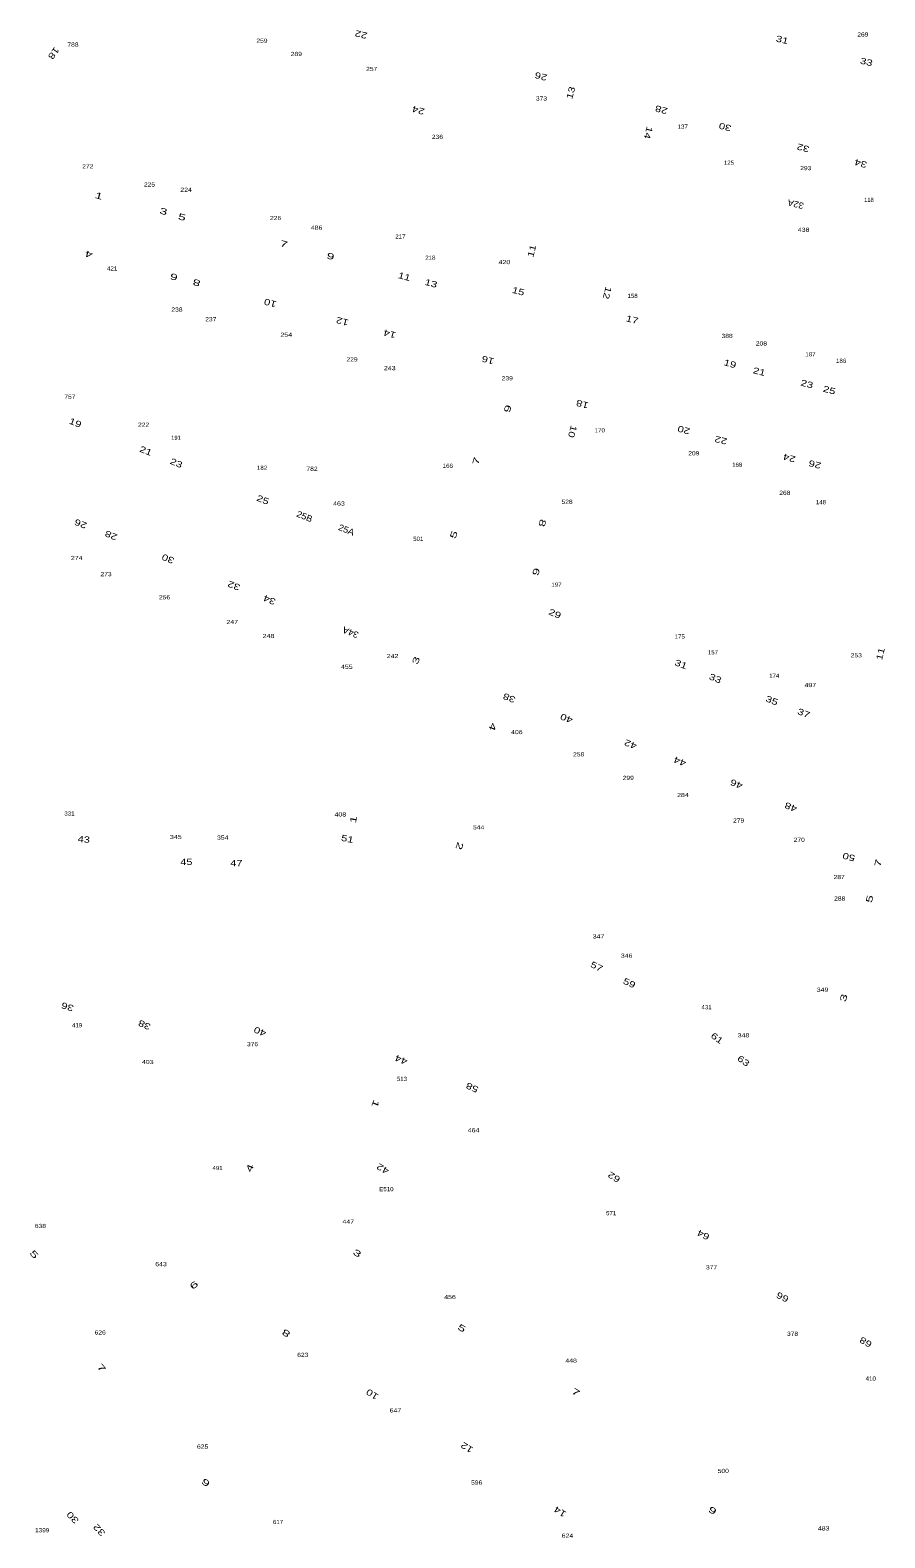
# Model space of a CAD drawing. Extents: x -828673 to -815583, y -1077737 to -1063807.
# Drawn here: x -818529 to -818324.1, y -1069307.9 to -1068946.4 of the extents above; entities that cross this region are included whole.
import ezdxf
from ezdxf.enums import TextEntityAlignment as Align

# ---------------------------------------------------------------- set-up
doc = ezdxf.new("R2010")
doc.units = 0
doc.header["$LTSCALE"] = 0.4
doc.layers.add('1', color=7, linetype='Continuous')
doc.layers.add('2', color=7, linetype='Continuous')

msp = doc.modelspace()

# ---------------------------------------------------------------- texts
at = {"layer": '1'}
for s, width, p in [('788', 1.2, (-818518.729, -1068950.34)), ('259', 1.2, (-818473.433, -1068949.416)), ('269', 1.2, (-818329.403, -1068947.924)), ('289', 1.2, (-818465.19, -1068952.588)), ('257', 1.2, (-818447.118, -1068956.183)), ('373', 1.2, (-818406.43, -1068963.268)), ('137', 1.1, (-818372.57, -1068970.008)), ('236', 1.2, (-818431.371, -1068972.467)), ('125', 1.1, (-818361.499, -1068978.661)), ('272', 1.2, (-818515.178, -1068979.552)), ('293', 1.2, (-818343.075, -1068979.959)), ('225', 1.2, (-818500.382, -1068983.887)), ('224', 1.25, (-818491.61, -1068985.156)), ('226', 1.2, (-818470.157, -1068991.924)), ('486', 1.25, (-818460.328, -1068994.25)), ('217', 1.1, (-818440.248, -1068996.365)), ('438', 1.25, (-818343.594, -1068994.757)), ('421', 1.1, (-818509.34, -1069004.03)), ('218', 1.1, (-818433.062, -1069001.44)), ('420', 1.25, (-818415.307, -1069002.498)), ('158', 1.1, (-818384.593, -1069010.593)), ('238', 1.2, (-818493.805, -1069013.889)), ('237', 1.2, (-818485.69, -1069016.209)), ('254', 1.25, (-818467.605, -1069019.92)), ('388', 1.2, (-818361.931, -1069020.198)), ('208', 1.2, (-818353.714, -1069022.016)), ('229', 1.2, (-818451.838, -1069025.836)), ('187', 1.1, (-818341.951, -1069024.612)), ('186', 1.1, (-818334.599, -1069026.169)), ('243', 1.25, (-818442.795, -1069027.923)), ('239', 1.2, (-818414.624, -1069030.359)), ('757', 1.2, (-818519.462, -1069034.769)), ('222', 1.2, (-818501.805, -1069041.494)), ('170', 1.1, (-818392.441, -1069042.838)), ('182', 1.1, (-818473.401, -1069051.817)), ('166', 1.1, (-818428.883, -1069051.353)), ('209', 1.2, (-818369.912, -1069048.346)), ('168', 1.1, (-818359.513, -1069051.1)), ('782', 1.2, (-818461.426, -1069052.068)), ('268', 1.2, (-818348.095, -1069057.831)), ('463', 1.25, (-818454.968, -1069060.4)), ('528', 1.2, (-818400.291, -1069059.973)), ('148', 1.1, (-818339.43, -1069060.075)), ('501', 1.1, (-818435.955, -1069068.867)), ('274', 1.25, (-818517.817, -1069073.454)), ('273', 1.2, (-818510.803, -1069077.328)), ('197', 1.1, (-818402.84, -1069079.862)), ('256', 1.2, (-818496.775, -1069082.884)), ('247', 1.25, (-818480.554, -1069088.805)), ('248', 1.25, (-818471.86, -1069092.167)), ('175', 1.1, (-818373.276, -1069092.305)), ('242', 1.25, (-818442.107, -1069096.974)), ('157', 1.1, (-818365.324, -1069096.079)), ('253', 1.2, (-818330.969, -1069096.793)), ('455', 1.25, (-818453.082, -1069099.551)), ('174', 1.1, (-818350.644, -1069101.688)), ('497', 1.25, (-818341.979, -1069103.932)), ('406', 1.25, (-818412.334, -1069115.2)), ('258', 1.2, (-818397.516, -1069120.534)), ('299', 1.2, (-818385.632, -1069126.19)), ('284', 1.25, (-818372.526, -1069130.303)), ('331', 1.1, (-818519.574, -1069134.733)), ('408', 1.25, (-818454.625, -1069134.958)), ('544', 1.2, (-818421.487, -1069138.039)), ('279', 1.2, (-818359.164, -1069136.409)), ('345', 1.25, (-818494.074, -1069140.362)), ('354', 1.25, (-818482.822, -1069140.508)), ('270', 1.2, (-818344.646, -1069141.037)), ('287', 1.2, (-818335.074, -1069149.97)), ('288', 1.2, (-818334.945, -1069155.112)), ('347', 1.25, (-818392.758, -1069164.203)), ('346', 1.25, (-818386.012, -1069168.83)), ('349', 1.25, (-818339.052, -1069176.993)), ('431', 1.1, (-818366.858, -1069181.181)), ('419', 1.1, (-818517.732, -1069185.507)), ('348', 1.25, (-818358.003, -1069187.919)), ('376', 1.2, (-818475.68, -1069190.039)), ('403', 1.25, (-818500.791, -1069194.321)), ('513', 1.1, (-818439.87, -1069198.371)), ('464', 1.25, (-818422.703, -1069210.688)), ('491', 1.1, (-818484.076, -1069219.744)), ('E510', 1.1, (-818443.597, -1069224.812)), ('447', 1.25, (-818452.745, -1069232.608)), ('571', 1.1, (-818389.725, -1069230.574)), ('638', 1.2, (-818526.542, -1069233.642)), ('643', 1.25, (-818497.629, -1069242.795)), ('377', 1.2, (-818365.669, -1069243.569)), ('456', 1.25, (-818428.35, -1069250.687)), ('626', 1.2, (-818512.198, -1069259.179)), ('378', 1.2, (-818346.243, -1069259.501)), ('623', 1.2, (-818463.643, -1069264.555)), ('448', 1.25, (-818399.325, -1069265.941)), ('410', 1.1, (-818327.496, -1069270.235)), ('647', 1.25, (-818441.434, -1069277.871)), ('625', 1.2, (-818487.646, -1069286.541)), ('596', 1.2, (-818421.961, -1069295.176)), ('617', 1.1, (-818469.571, -1069304.624)), ('1399', 1.15, (-818526.1, -1069306.601)), ('624', 1.25, (-818400.205, -1069307.921)), ('483', 1.25, (-818338.79, -1069306.167))]:
    msp.add_text(s, height=1, dxfattribs=dict(at, width=width)).set_placement(p, align=Align.CENTER)
for s, p in [('118', (-818327.939, -1068987.575)), ('191', (-818494.037, -1069044.625))]:
    msp.add_text(s, height=1, dxfattribs=at).set_placement(p, align=Align.CENTER)
at = {"layer": '1', "width": 1.2}
msp.add_text('500', height=1, rotation=1.052, dxfattribs=at).set_placement((-818362.8452, -1069292.3815), align=Align.CENTER)
at = {"layer": '2'}
for s, rotation, width, p in [('22', 166.292, 1.35, (-818449.4943, -1068946.708)), ('31', 346.203, 1.35, (-818348.9144, -1068949.4182)), ('18', 235.339, 1.35, (-818523.9675, -1068951.4835)), ('33', 346.163, 1.35, (-818328.7274, -1068954.7113)), ('26', 165.53, 1.35, (-818406.3756, -1068956.7494)), ('13', 75.223, 1.35, (-818398.6946, -1068961.5943)), ('24', 164.516, 1.35, (-818435.7548, -1068964.8875)), ('28', 165.241, 1.35, (-818377.5029, -1068964.747)), ('14', 254.745, 1.35, (-818381.5298, -1068970.7757)), ('30', 164.604, 1.35, (-818362.2164, -1068968.8907)), ('32', 165.157, 1.35, (-818343.5334, -1068973.9119)), ('34', 164.233, 1.35, (-818329.6952, -1068977.6292)), ('1', 344.093, 1.65, (-818512.7236, -1068986.8243)), ('3', 344.831, 1.65, (-818497.2197, -1068990.5557)), ('32A', 165.847, 1.1, (-818345.3241, -1068987.4011)), ('5', 345.192, 1.65, (-818492.7802, -1068991.9268)), ('4', 165.192, 1.65, (-818514.7478, -1068999.3952)), ('7', 344.838, 1.65, (-818468.3677, -1068998.3806)), ('9', 345.57, 1.65, (-818457.1649, -1069001.3348)), ('11', 75.183, 1.35, (-818408.0345, -1068999.5213)), ('6', 165.1, 1.65, (-818494.3442, -1069004.8456)), ('8', 164.922, 1.65, (-818488.8954, -1069006.2368)), ('11', 344.636, 1.35, (-818439.5042, -1069006.1915)), ('13', 344.87, 1.35, (-818433.0898, -1069007.8146)), ('10', 165.243, 1.35, (-818471.243, -1069011.0871)), ('15', 345.227, 1.35, (-818412.1642, -1069009.7133)), ('12', 255.8, 1.35, (-818391.3817, -1069009.198)), ('12', 165.248, 1.35, (-818453.969, -1069015.4952)), ('14', 164.781, 1.35, (-818442.6076, -1069018.5052)), ('17', 346.02, 1.35, (-818384.8622, -1069016.5169)), ('16', 165.24, 1.35, (-818419.0739, -1069024.774)), ('19', 344.368, 1.35, (-818361.4241, -1069027.0893)), ('21', 345.489, 1.35, (-818354.4164, -1069028.9837)), ('23', 345.111, 1.35, (-818342.9857, -1069031.9513)), ('25', 345.111, 1.35, (-818337.6237, -1069033.4223)), ('9', 74.573, 1.65, (-818413.8123, -1069037.361)), ('18', 164.63, 1.35, (-818396.4157, -1069035.3553)), ('19', 338.094, 1.35, (-818518.4458, -1069041.2294)), ('10', 254.985, 1.35, (-818399.7134, -1069042.4282)), ('20', 164.649, 1.35, (-818372.1119, -1069041.5418)), ('21', 338.59, 1.35, (-818501.5388, -1069047.953)), ('22', 166.314, 1.35, (-818363.2416, -1069043.9976)), ('23', 337.745, 1.35, (-818494.2385, -1069050.8803)), ('7', 74.734, 1.65, (-818421.3489, -1069049.8865)), ('24', 164.465, 1.35, (-818346.8286, -1069048.2731)), ('26', 165.579, 1.35, (-818340.7117, -1069049.8087)), ('25', 338.323, 1.35, (-818473.487, -1069059.6927)), ('26', 158.749, 1.35, (-818516.6187, -1069064.068)), ('25B', 338.321, 1.1, (-818463.4761, -1069063.6973)), ('25A', 338.437, 1.1, (-818453.4616, -1069066.8955)), ('8', 254.661, 1.65, (-818406.9324, -1069064.3736)), ('28', 157.813, 1.35, (-818509.3118, -1069066.8405)), ('5', 69.044, 1.65, (-818426.7532, -1069067.6377)), ('30', 157.949, 1.35, (-818495.6704, -1069072.4617)), ('6', 248.381, 1.65, (-818408.4083, -1069075.9942)), ('32', 158.921, 1.35, (-818479.8883, -1069078.8992)), ('34', 157.627, 1.35, (-818471.3395, -1069082.3277)), ('29', 337.694, 1.35, (-818403.4952, -1069087.0065)), ('34A', 157.95, 1.1, (-818451.9129, -1069090.1219)), ('3', 67.76, 1.65, (-818435.8158, -1069097.8194)), ('31', 338.868, 1.35, (-818373.2644, -1069099.1371)), ('11', 75.986, 1.35, (-818324.4601, -1069096.1391)), ('33', 337.554, 1.35, (-818365.0394, -1069102.519)), ('38', 158.995, 1.35, (-818413.9037, -1069105.8351)), ('35', 338.287, 1.35, (-818351.48, -1069107.8197)), ('40', 158.092, 1.35, (-818400.1542, -1069110.7235)), ('37', 338.499, 1.35, (-818343.8354, -1069110.8783)), ('4', 248.176, 1.65, (-818418.7965, -1069113.1732)), ('42', 158.608, 1.35, (-818384.8004, -1069116.9604)), ('44', 157.913, 1.35, (-818372.9805, -1069121.0701)), ('46', 158.227, 1.35, (-818359.4253, -1069126.4699)), ('48', 158.399, 1.35, (-818346.3849, -1069131.9991)), ('1', 78.883, 1.65, (-818450.7664, -1069135.8201)), ('43', 355.855, 1.3, (-818516.1762, -1069141.1843)), ('51', 348.541, 1.35, (-818453.0855, -1069141.0499)), ('2', 252.255, 1.65, (-818426.7768, -1069141.7909)), ('50', 165.591, 1.35, (-818332.5724, -1069143.9251)), ('45', 359.593, 1.3, (-818491.5573, -1069146.5785)), ('47', 358.698, 1.3, (-818479.574, -1069146.8736)), ('7', 77.391, 1.65, (-818325.0214, -1069146.2697)), ('5', 76.719, 1.65, (-818327.0716, -1069154.8823)), ('57', 333.635, 1.35, (-818393.5261, -1069171.5931)), ('59', 335.194, 1.35, (-818385.6872, -1069175.5704)), ('36', 162.922, 1.35, (-818519.8247, -1069179.8816)), ('3', 75.696, 1.65, (-818333.2912, -1069178.6278)), ('38', 156.522, 1.35, (-818501.2992, -1069184.2545)), ('40', 156.522, 1.35, (-818473.5992, -1069185.8355)), ('61', 324.086, 1.35, (-818364.7924, -1069188.7087)), ('44', 157.982, 1.35, (-818439.7923, -1069192.6167)), ('63', 323.95, 1.35, (-818358.4464, -1069194.1527)), ('58', 156.043, 1.35, (-818422.739, -1069199.2715)), ('1', 248.15, 1.65, (-818446.9078, -1069203.5419)), ('4', 66.935, 1.65, (-818475.6558, -1069219.5563)), ('42', 149.601, 1.35, (-818444.0795, -1069218.7862)), ('62', 148.079, 1.35, (-818388.6394, -1069220.8024)), ('64', 152.868, 1.35, (-818367.2985, -1069234.6145)), ('3', 328.286, 1.7, (-818450.9953, -1069240.3106)), ('5', 311.545, 1.75, (-818528.591, -1069240.4471)), ('6', 41.564, 1.75, (-818489.2461, -1069247.8958)), ('66', 153.801, 1.35, (-818348.3264, -1069249.5341)), ('5', 328.233, 1.7, (-818425.9229, -1069258.2763)), ('8', 147.591, 1.7, (-818467.248, -1069258.2277)), ('68', 149.744, 1.35, (-818328.3326, -1069260.359)), ('7', 311.637, 1.75, (-818512.4397, -1069267.6772)), ('10', 147.29, 1.35, (-818446.5832, -1069272.888)), ('7', 328.507, 1.7, (-818398.5903, -1069273.6415)), ('12', 147.938, 1.35, (-818423.8949, -1069285.6359)), ('9', 319.846, 1.75, (-818487.3996, -1069295.2742)), ('30', 133.5, 1.4, (-818518.2652, -1069302.5583)), ('14', 147.691, 1.35, (-818401.5726, -1069301.0432)), ('9', 328.141, 1.7, (-818365.8389, -1069302.0061)), ('32', 132.738, 1.4, (-818511.8995, -1069305.56))]:
    msp.add_text(s, height=1.5, rotation=rotation, dxfattribs=dict(at, width=width)).set_placement(p, align=Align.CENTER)

doc.saveas('drawing.dxf')
